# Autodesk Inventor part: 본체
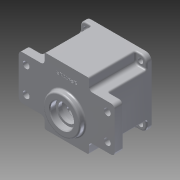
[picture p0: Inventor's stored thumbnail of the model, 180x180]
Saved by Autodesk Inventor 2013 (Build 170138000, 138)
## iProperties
Created: 2015-07
Part Number: 본체
Material: 알루미늄 6061
Document SubType Name: Modeling
Designer: user
Density: 2.71 g/cm^3
Mass: 705.327 g
Surface Area: 673.076 cm^2
Volume: 260.268 cm^3
Author: user
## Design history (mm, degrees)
sketch "스케치1"
  geometry: L1 (-30, -45)-(30, -45); L2 (30, 45)-(-30, 45); L3 (65, -30)-(65, 30); L4 (-65, 30)-(-65, -30); L5 (-65, -30)-(-30, -30); L6 (30, -30)-(65, -30); L7 (30, -45)-(30, -30); L8 (30, 30)-(30, 45); L9 (-30, 45)-(-30, 30); L10 (-30, -30)-(-30, -45); L11 (65, 30)-(30, 30); L12 (-30, 30)-(-65, 30); 5 further points
  constraints: 24 end point, 10 parallel, 4 perpendicular, 3 horizontal, 2 horizontal alignment, 2 midpoint, 2 vertical alignment
  dimensions: "d0" = 60 distance of L2.end L2.start; "d1" = 90 distance of L2.start L1.end; "d2" = 130 distance of L4.start L3.end; "d3" = 60 distance of L3.end L3.start; "d4" = 35 distance between parallel lines of L3 L8; "d5" = 35 distance between parallel lines of L3 L7; "d6" = 95 distance between parallel lines of L3 L10; "d7" = 130 distance between parallel lines of L3 L4; "d8" = 15 distance between parallel lines of L11 L2; "d9" = 60 distance between parallel lines of L11 L5; "d10" = 35 distance from line of point (30, 0) L3; "d11" = 0 distance from line of point (0, 30) L11
extrude "돌출1" new body sketch "스케치1" distance "d12" = 12; taper "d13" = 0 deg
sketch "스케치2"
  geometry: L1 (-30, 30)-(-65, 30) reference; L2 (-65, -30)-(-30, -30) reference; L3 (30, -30)-(65, -30) reference; L4 (65, -30)-(65, 30) reference; L5 (65, 30)-(30, 30) reference; L6 (30, 30)-(30, 45) reference; L7 (-30, -45)-(30, -45); L8 (45, -30)-(45, 30); L9 (30, 45)-(-30, 45); L10 (-45, 30)-(-45, -30); L11 (-45, 30)-(-30, 30); L12 (30, 30)-(45, 30); L13 (-45, -30)-(-30, -30); L14 (30, -30)-(45, -30); L15 (-30, -45)-(-30, -30); L16 (-30, 30)-(-30, 45); L17 (30, 45)-(30, 30); L18 (30, -30)-(30, -45); 3 further points
  constraints: 25 end point, 8 point on line, 4 equal length, 3 perpendicular, 2 midpoint, 1 horizontal, 1 horizontal alignment, 1 vertical alignment
  dimensions: "d16" = 90 deg angle of L4 L14; "d17" = 90 deg angle of L4 L11; "d18" = 90 deg angle of L4 L13; "d19" = 15 distance between parallel lines of L5 L9; "d20" = 75 distance between parallel lines of L5 L7; "d21" = 20 distance between parallel lines of L4 L8; "d22" = 110 distance between parallel lines of L4 L10
extrude "돌출2" join sketch "스케치2" distance "d23" = 51; taper "d24" = 0 deg
sketch "스케치3"
  geometry: L1 (-45, -45)-(45, -45); L2 (45, -45)-(45, 45); L3 (45, 45)-(-45, 45); L4 (-45, 45)-(-45, -45); 3 further points
  constraints: 8 end point, 2 midpoint, 2 parallel, 1 horizontal, 1 horizontal alignment, 1 perpendicular, 1 vertical alignment
  dimensions: "d25" = 90 distance of L3.end L2.end; "d26" = 90 distance of L2.end L1.end
extrude "돌출3" join sketch "스케치3" distance "d27" = 7; taper "d28" = 0 deg
sketch "스케치4"
  geometry: C1 r 40 at (0, 0); 1 further point
  constraints: 1 centre point, 1 coincident
  dimensions: "d29" = 80 diameter of C1
extrude "돌출4" cut sketch "스케치4" distance "d30" = 9; taper "d31" = 0 deg
sketch "스케치5"
  geometry: L1 (0, 0)-(-30.722, 30.722); L2 (0, 0)-(43.447, 0); C1 r 40 at (0, 0) reference; A1 r 35 centre (0, 0) between (-24.749, 24.749) and (-27.412, 21.762); A2 r 4 centre (-24.749, 24.749) between (-27.462, 21.809) and (-21.809, 27.462); A3 r 3.5 centre (-29.836, 19.238) between (-27.412, 21.762) and (-32.777, 21.134); A4 r 3.5 centre (-19.238, 29.836) between (-21.134, 32.777) and (-21.762, 27.412); A5 r 4 centre (-24.749, -24.749) between (-21.809, -27.462) and (-27.462, -21.809); A6 r 3.5 centre (-29.836, -19.238) between (-32.777, -21.134) and (-27.412, -21.762); A7 r 3.5 centre (-19.238, -29.836) between (-21.762, -27.412) and (-21.134, -32.777); A8 r 4 centre (24.749, -24.749) between (27.462, -21.809) and (21.809, -27.462); A9 r 3.5 centre (19.238, -29.836) between (21.134, -32.777) and (21.762, -27.412); A10 r 3.5 centre (29.836, -19.238) between (27.412, -21.762) and (32.777, -21.134); A11 r 4 centre (24.749, 24.749) between (21.809, 27.462) and (27.462, 21.809); A12 r 3.5 centre (29.836, 19.238) between (32.777, 21.134) and (27.412, 21.762); A13 r 3.5 centre (19.238, 29.836) between (21.762, 27.412) and (21.134, 32.777); A14 r 39 centre (0, 0) between (21.134, 32.777) and (-21.134, 32.777); A15 r 39 centre (0, 0) between (32.777, -21.134) and (32.777, 21.134); A16 r 39 centre (0, 0) between (-32.777, 21.134) and (-32.777, -21.134); A17 r 39 centre (0, 0) between (-21.134, -32.777) and (21.134, -32.777)
  constraints: 43 point on circle, 17 centre point, 5 tangent, 4 end point, 2 coincident, 1 equal length, 1 horizontal, 1 point on line, 49 other
  dimensions: "d33" = 70 diameter of A1; "d34" = 135 deg angle of L2 L1; "d35" = 8 diameter of A2; "d36" = 7 diameter of A3; "d37" = 7 diameter of A4; "d40" = 360 deg dimension on C1.centre A1.start (derived); "d42" = 30.72189 distance from line of L2.end L1
extrude "돌출5" cut sketch "스케치5" distance "d43" = 52; taper "d44" = 0 deg
sketch "스케치6"
  geometry: L1 (0, 0)-(0, 11); L2 (0, 0)-(0, -20); L3 (0, 0)-(20, 0); A1 r 35 centre (0, 0) between (-21.762, 27.412) and (-27.412, 21.762) reference; A2 r 14 centre (0, -20) between (-7.402, -8.117) and (7.402, -8.117); A3 r 20.5 centre (0, 11) between (7.402, -8.117) and (-7.402, -8.117)
  constraints: 6 end point, 4 point on circle, 2 centre point, 2 coincident, 1 collinear, 1 horizontal, 1 perpendicular, 1 vertical
  dimensions: "d45" = 11 distance of L1.start L1.end; "d48" = 20 distance of L1.start L2.end; "d49" = 90 deg angle of L2 L3 (derived); "d50" = 28 diameter of A2; "d52" = 20.5 radius of A3
extrude "돌출6" join sketch "스케치6" distance "d53" = 7; taper "d54" = 0 deg
sketch "스케치7"
  geometry: C1 r 17.5 at (0, 11); A1 r 20.5 centre (0, 11) between (7.402, -8.117) and (-7.402, -8.117) reference; 1 further point
  constraints: 1 centre point, 1 coincident
  dimensions: "d55" = 35 diameter of C1
extrude "돌출7" cut sketch "스케치7" distance "d56" = 10; taper "d57" = 0 deg
sketch "스케치8"
  geometry: C1 r 17.5 at (0, 0) reference; C2 r 12.5 at (0, 0); 1 further point
  constraints: 1 centre point, 1 coincident
  dimensions: "d58" = 25 diameter of C2
extrude "돌출8" cut sketch "스케치8" distance "d59" = 124; taper "d60" = 0 deg
sketch "스케치9"
  geometry: C1 r 12.5 at (0, -11) reference; C2 r 25 at (0, -11); 1 further point
  constraints: 1 centre point, 1 coincident
  dimensions: "d61" = 50 diameter of C2
extrude "돌출9" join sketch "스케치9" distance "d62" = 7; taper "d63" = 0 deg
sketch "스케치10"
  geometry: C1 r 12.5 at (0, 0) reference; C2 r 25 at (0, 0) reference; C3 r 16 at (0, 0); 1 further point
  constraints: 1 centre point, 1 coincident
  dimensions: "d64" = 32 diameter of C3
extrude "돌출10" cut sketch "스케치10" distance "d65" = 7; taper "d66" = 0 deg
sketch "스케치11"
  geometry: C1 r 11 at (0, -20); A1 r 14 centre (0, -20) between (-7.402, -8.117) and (7.402, -8.117) reference; 1 further point
  constraints: 1 centre point, 1 coincident
  dimensions: "d67" = 22 diameter of C1
extrude "돌출11" cut sketch "스케치11" distance "d68" = 7; taper "d69" = 0 deg
sketch "스케치12"
  geometry: C1 r 11 at (0, 0) reference; C2 r 9.5 at (0, 0); 1 further point
  constraints: 1 centre point, 1 coincident
  dimensions: "d70" = 19 diameter of C2
extrude "돌출12" cut sketch "스케치12" distance "d71" = 1; taper "d72" = 0 deg
sketch "스케치13"
  geometry: C1 r 12.5 at (0, 0) reference; C2 r 16 at (0, 0) reference; 1 further point
extrude "돌출13" cut sketch "스케치13" distance "d73" = 1; taper "d74" = 0 deg
sketch "스케치14"
  geometry: L1 (-30, 45)-(30, 45) reference; L2 (-30, -45)-(-30, -30) reference; L3 (0, 45)-(0, 30); 2 further points
  constraints: 2 end point, 1 coincident, 1 midpoint, 1 parallel, 1 other
  dimensions: "d75" = 15 distance of L3.start L3.end
feature "엠보싱1" sketch "스케치14" dims "d0" = 60, "d1" = 90, "d2" = 130, "d3" = 60, "d4" = 35, "d5" = 35, "d6" = 95, "d7" = 130, "d8" = 15, "d9" = 60, "d10" = 35, "d11" = 0, "d76" = 0.5, "d77" = 0
sketch "스케치15"
  geometry: C1 r 4 at (24.749, 24.749); C2 r 4 at (-24.749, 24.749); A1 r 3.5 centre (-29.836, 19.238) between (-27.412, 21.762) and (-32.777, 21.134) reference; A2 r 3.5 centre (-19.238, 29.836) between (-21.134, 32.777) and (-21.762, 27.412) reference; A3 r 4 centre (24.749, 24.749) between (21.809, 27.462) and (27.462, 21.809) reference; A4 r 39 centre (0, 0) between (-21.134, -32.777) and (21.134, -32.777) reference
  constraints: 3 tangent, 2 centre point, 1 coincident, 1 concentric
extrude "돌출14" join sketch "스케치15" distance "d78" = 52; taper "d79" = 0 deg
sketch "스케치16"
  geometry: A1 r 4 centre (24.749, 24.749) between (21.809, 27.462) and (27.462, 21.809) reference; A2 r 4 centre (24.749, -24.749) between (27.462, -21.809) and (21.809, -27.462) reference; A3 r 4 centre (-24.749, -24.749) between (-21.809, -27.462) and (-27.462, -21.809) reference; A4 r 4 centre (-24.749, 24.749) between (-27.411, 21.763) and (-21.763, 27.411) reference; 4 further points
  constraints: 4 coincident
hole "구멍1" sketch "스케치16" at (-24.749, 24.749), (-24.749, -24.749), (24.749, -24.749), (24.749, 24.749) diameter "d80" = 3.459; stored, may be unused: countersink angle "d84" = 90 deg, drill point angle "d86" = 118 deg; dims "d81" = 12, "d82" = 4, "d83" = 2, "d85" = 15
fillet "모깎기1" dims "d87" = 5
fillet "모깎기2" dims "d88" = 5
fillet "모깎기3" dims "d89" = 8
chamfer "모따기1" distance "d95" = 1; stored, may be unused: second distance "d96" = 2, angle "d97" = 45 deg
fillet "모깎기9" dims "d98" = 0.3
fillet "모깎기10" dims "d99" = 2
sketch "스케치17"
  geometry: L1 (30, 45)-(30, 35) reference; L2 (35, 30)-(45, 30) reference; L3 (45, -30)-(35, -30) reference; L4 (30, -35)-(30, -45) reference; L5 (-30, -45)-(-30, -35) reference; L6 (-35, -30)-(-45, -30) reference; L7 (-30, 35)-(-30, 45) reference; L8 (-45, 30)-(-35, 30) reference; L9 (60, 30)-(47, 30) reference; L10 (-13.292, -30.002)-(-12.362, -30.002) reference; L11 (-12.362, -30.002)-(-12.362, -29.736) reference; L12 (-12.362, -29.736)-(-13.292, -29.736) reference; L13 (-13.292, -29.736)-(-13.292, -27.932) reference; L14 (-13.292, -27.932)-(-13.52, -27.932) reference; L15 (-13.615, -28.117)-(-13.615, -32.087) reference; L16 (-13.615, -32.087)-(-13.292, -32.087) reference; L17 (-13.292, -32.087)-(-13.292, -30.002) reference; L18 (9.759, -29.546)-(9.759, -29.822) reference; L19 (9.759, -29.822)-(10.543, -29.822) reference; L20 (10.543, -29.822)-(10.543, -31.042) reference; L21 (10.543, -31.042)-(10.875, -31.042) reference; L22 (10.875, -31.042)-(10.875, -27.899) reference; L23 (10.875, -27.899)-(10.661, -27.899) reference; L24 (10.543, -28.084)-(10.543, -29.546) reference; L25 (10.543, -29.546)-(9.759, -29.546) reference; L26 (10.391, -31.707)-(10.391, -31.973) reference; L27 (10.391, -31.973)-(13.435, -31.973) reference; L28 (13.435, -31.973)-(13.435, -30.833) reference; L29 (13.435, -30.833)-(13.188, -30.833) reference; L30 (13.112, -30.985)-(13.112, -31.707) reference; L31 (13.112, -31.707)-(10.391, -31.707) reference; L32 (12.162, -28.302)-(13.197, -28.302) reference; L33 (13.197, -28.302)-(13.197, -28.055) reference; L34 (13.197, -28.055)-(12.162, -28.055) reference; L35 (12.162, -28.055)-(12.162, -28.302) reference; L36 (14.033, -28.867)-(14.033, -28.62) reference; L37 (14.033, -28.62)-(11.398, -28.62) reference; L38 (11.398, -28.62)-(11.398, -28.867) reference; L39 (11.398, -28.867)-(14.033, -28.867) reference; L40 (2.042, -31.831)-(2.431, -30.762) reference; L41 (2.431, -30.762)-(4.008, -30.762) reference; L42 (4.008, -30.762)-(4.407, -31.831) reference; L43 (4.407, -31.831)-(4.744, -31.831) reference; L44 (4.744, -31.831)-(3.415, -28.331) reference; L45 (3.415, -28.331)-(3.035, -28.331) reference; L46 (3.035, -28.331)-(1.705, -31.831) reference; L47 (1.705, -31.831)-(2.042, -31.831) reference; L48 (7.066, -30.596)-(5.799, -30.596) reference; L49 (5.799, -30.596)-(5.799, -32.082) reference; L50 (5.799, -32.082)-(6.121, -32.082) reference; L51 (6.121, -32.082)-(6.121, -30.857) reference; L52 (6.121, -30.857)-(8.805, -30.857) reference; L53 (8.805, -30.857)-(8.805, -30.596) reference; L54 (8.805, -30.596)-(7.385, -30.596) reference; L55 (7.385, -30.596)-(7.385, -29.741) reference; L56 (7.385, -29.741)-(9.318, -29.741) reference; L57 (9.318, -29.741)-(9.318, -29.48) reference; L58 (9.318, -29.48)-(6.259, -29.48) reference; L59 (6.06, -28.312)-(8.724, -28.312) reference; L60 (8.724, -28.312)-(8.724, -28.046) reference; L61 (8.724, -28.046)-(5.723, -28.046) reference; L62 (5.912, -29.48)-(5.115, -29.48) reference; L63 (5.115, -29.48)-(5.115, -29.741) reference; L64 (5.115, -29.741)-(7.066, -29.741) reference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; C1 r 11 at (0, -20) reference; C2 r 17.5 at (0, 11) reference; C3 r 25 at (0, 11) reference; A1 r 5 centre (35, 35) between (30, 35) and (35, 30) reference; A2 r 5 centre (35, -35) between (35, -30) and (30, -35) reference; A3 r 5 centre (-35, -35) between (-30, -35) and (-35, -30) reference; A4 r 5 centre (-35, 35) between (-35, 30) and (-30, 35) reference; A5 r 20.5 centre (0, 11) between (7.402, -8.117) and (-7.402, -8.117) reference; A6 r 14 centre (0, -20) between (-7.402, -8.117) and (7.402, -8.117) reference; A7 r 39 centre (0, 0) between (-32.777, 21.134) and (-32.777, -21.134) reference; A8 r 3.5 centre (-29.836, -19.238) between (-32.777, -21.134) and (-27.462, -21.809) reference; A9 r 4 centre (-24.749, -24.749) between (-21.809, -27.462) and (-27.462, -21.809) reference; A10 r 3.5 centre (-19.238, -29.836) between (-21.809, -27.462) and (-21.134, -32.777) reference; A11 r 39 centre (0, 0) between (-21.134, -32.777) and (21.134, -32.777) reference; A12 r 3.5 centre (19.238, -29.836) between (21.134, -32.777) and (21.809, -27.462) reference; A13 r 4 centre (24.749, -24.749) between (27.462, -21.809) and (21.809, -27.462) reference; A14 r 3.5 centre (29.836, -19.238) between (27.462, -21.809) and (32.777, -21.134) reference; A15 r 39 centre (0, 0) between (32.777, -21.134) and (32.777, 21.134) reference; A16 r 3.5 centre (29.836, 19.238) between (32.777, 21.134) and (27.462, 21.809) reference; A17 r 4 centre (24.749, 24.749) between (21.809, 27.462) and (27.462, 21.809) reference; A18 r 3.5 centre (19.238, 29.836) between (21.809, 27.462) and (21.134, 32.777) reference; A19 r 39 centre (0, 0) between (21.134, 32.777) and (-21.134, 32.777) reference; A20 r 3.5 centre (-19.238, 29.836) between (-21.134, 32.777) and (-21.762, 27.412) reference; A21 r 35 centre (0, 0) between (-21.762, 27.412) and (-21.763, 27.411) reference; A22 r 4 centre (-24.749, 24.749) between (-27.411, 21.763) and (-21.763, 27.411) reference; A23 r 35 centre (0, 0) between (-27.411, 21.763) and (-27.412, 21.762) reference; A24 r 3.5 centre (-29.836, 19.238) between (-27.412, 21.762) and (-32.777, 21.134) reference; A25 r 5 centre (-35, -35) between (-30, -35) and (-35, -30) reference; A26 r 5 centre (-60, -25) between (-65, -25) and (-60, -30) reference; A27 r 5 centre (-60, 25) between (-60, 30) and (-65, 25) reference; A28 r 5 centre (-35, 35) between (-35, 30) and (-30, 35) reference; A29 r 5 centre (35, 35) between (30, 35) and (35, 30) reference; A30 r 5 centre (60, 25) between (65, 25) and (60, 30) reference; A31 r 5 centre (60, -25) between (60, -30) and (65, -25) reference; A32 r 5 centre (35, -35) between (35, -30) and (30, -35) reference; A33 r 5 centre (-60, -25) between (-65, -25) and (-60, -30) reference; A34 r 5 centre (-60, 25) between (-60, 30) and (-65, 25) reference; A35 r 5 centre (60, 25) between (65, 25) and (60, 30) reference; A36 r 5 centre (60, -25) between (60, -30) and (65, -25) reference; 64 further points
  constraints: 8 end point, 4 coincident, 2 midpoint, 2 parallel, 1 horizontal, 1 horizontal alignment, 1 perpendicular, 1 vertical alignment, 68 other
  dimensions: "d100" = 110 distance of L121.end L120.end; "d101" = 35 distance of L120.end L119.end
hole "구멍2" sketch "스케치17" at (-55, 17.5), (-55, -17.5), (55, -17.5), (55, 17.5) diameter "d102" = 9; stored, may be unused: countersink angle "d106" = 90 deg, drill point angle "d108" = 118 deg; dims "d103" = 12, "d104" = 4, "d105" = 2, "d107" = 15
sketch "스케치18"
  geometry: L1 (35, 30)-(45, 30) reference; L2 (45, 30)-(45, -30) reference; L3 (45, -30)-(45, -37) reference; L4 (37, -45)-(30, -45) reference; L5 (30, -45)-(-30, -45) reference; L6 (-30, -45)-(-37, -45) reference; L7 (-45, -37)-(-45, -30) reference; L8 (-45, -30)-(-45, 30) reference; L9 (-45, 30)-(-35, 30) reference; L10 (-30, 35)-(-30, 45) reference; L11 (-37, 45)-(-30, 45) reference; L12 (-45, 30)-(-45, 37) reference; L13 (30, 45)-(30, 35) reference; L14 (-30, 45)-(30, 45) reference; L15 (45, 37)-(45, 30) reference; L16 (30, 45)-(37, 45) reference; L17 (45, -30)-(35, -30) reference; L18 (30, -35)-(30, -45) reference; L19 (-30, -45)-(-30, -35) reference; L20 (-35, -30)-(-45, -30) reference; C1 r 40 at (0, 0) reference; A1 r 5 centre (35, 35) between (30, 35) and (35, 30) reference; A2 r 8 centre (37, -37) between (37, -45) and (45, -37) reference; A3 r 8 centre (-37, -37) between (-45, -37) and (-37, -45) reference; A4 r 5 centre (-35, 35) between (-35, 30) and (-30, 35) reference; A5 r 8 centre (-37, 37) between (-37, 45) and (-45, 37) reference; A6 r 8 centre (37, 37) between (45, 37) and (37, 45) reference; A7 r 5 centre (35, -35) between (35, -30) and (30, -35) reference; A8 r 5 centre (-35, -35) between (-30, -35) and (-35, -30) reference; 5 further points
hole "구멍3" sketch "스케치18" at (-37, 37), (-37, -37), (37, -37), (37, 37) diameter "d109" = 7; stored, may be unused: countersink angle "d113" = 90 deg, drill point angle "d115" = 118 deg; dims "d110" = 12, "d111" = 4, "d112" = 2, "d114" = 15
fillet "모깎기11" dims "d116" = 2
fillet "모깎기12" dims "d117" = 3
fillet "모깎기13" dims "d118" = 2
fillet "모깎기14" dims "d119" = 2
fillet "모깎기15" dims "d120" = 2
fillet "모깎기16" dims "d121" = 2
node "솔리드1"
node "투영된 루프1"
node "절단 모서리 투영1"
node "절단 모서리 투영2"
other parameters: "d32" = 78, "d46" = 41
